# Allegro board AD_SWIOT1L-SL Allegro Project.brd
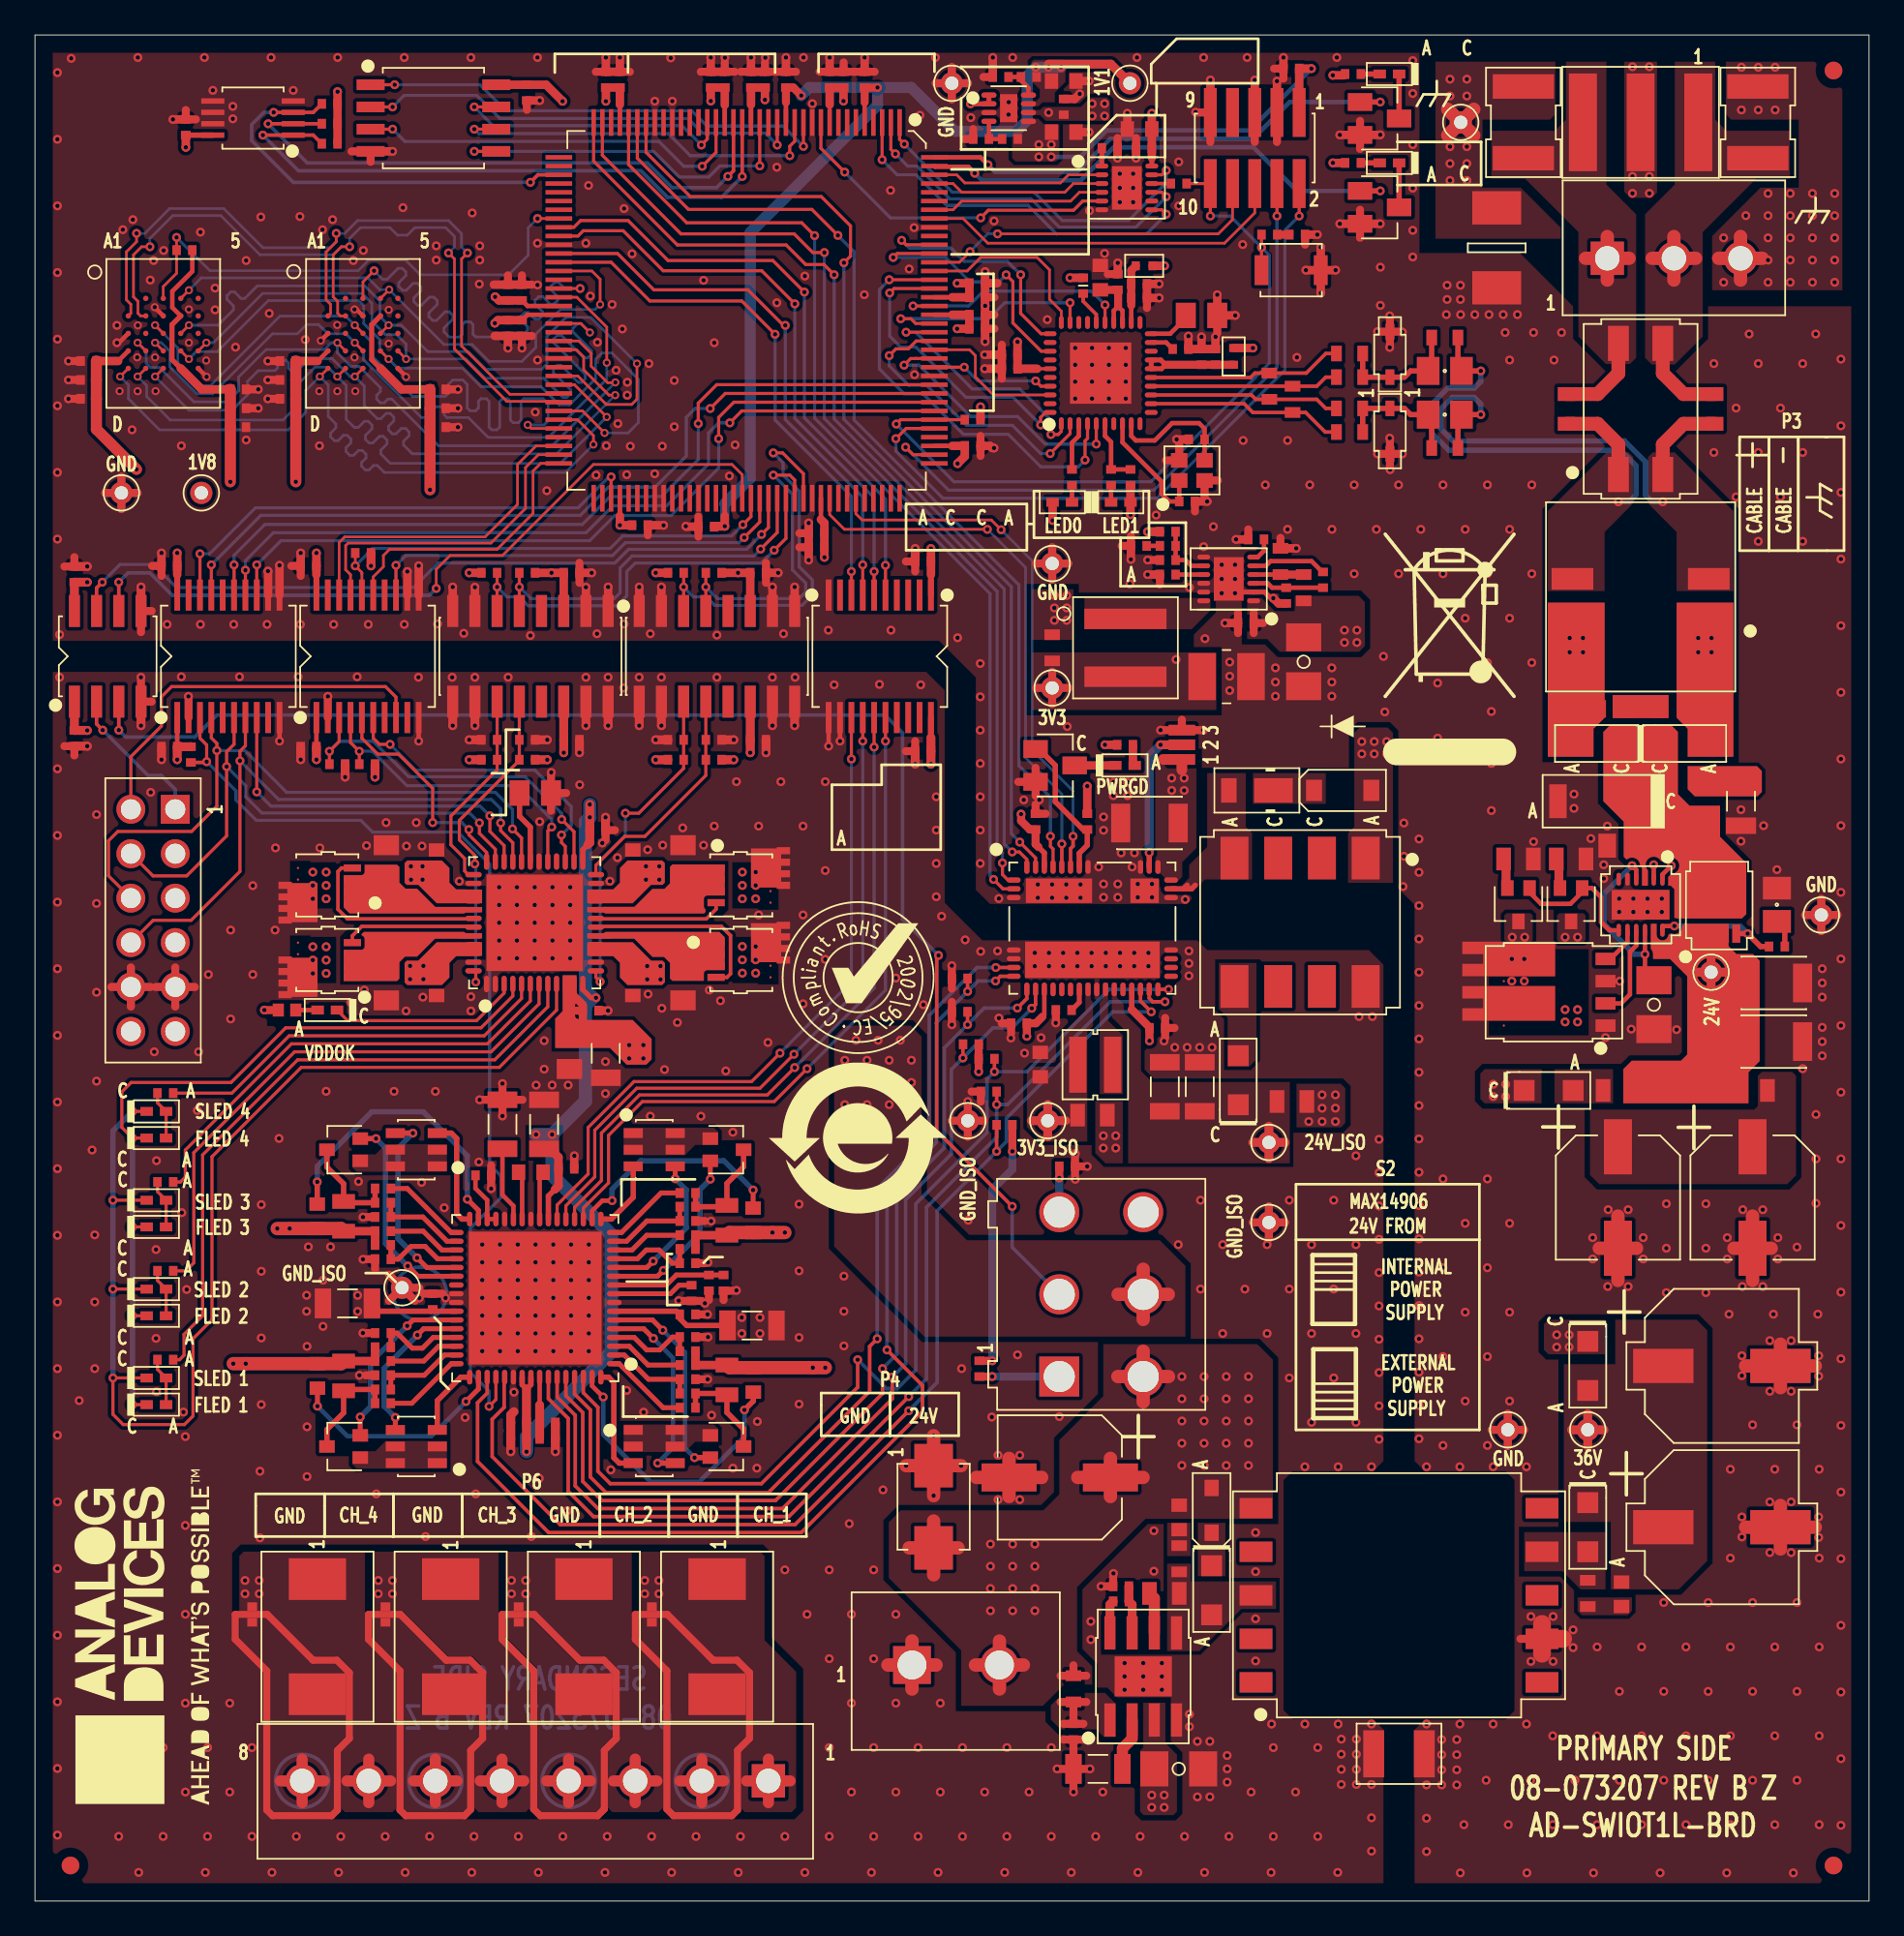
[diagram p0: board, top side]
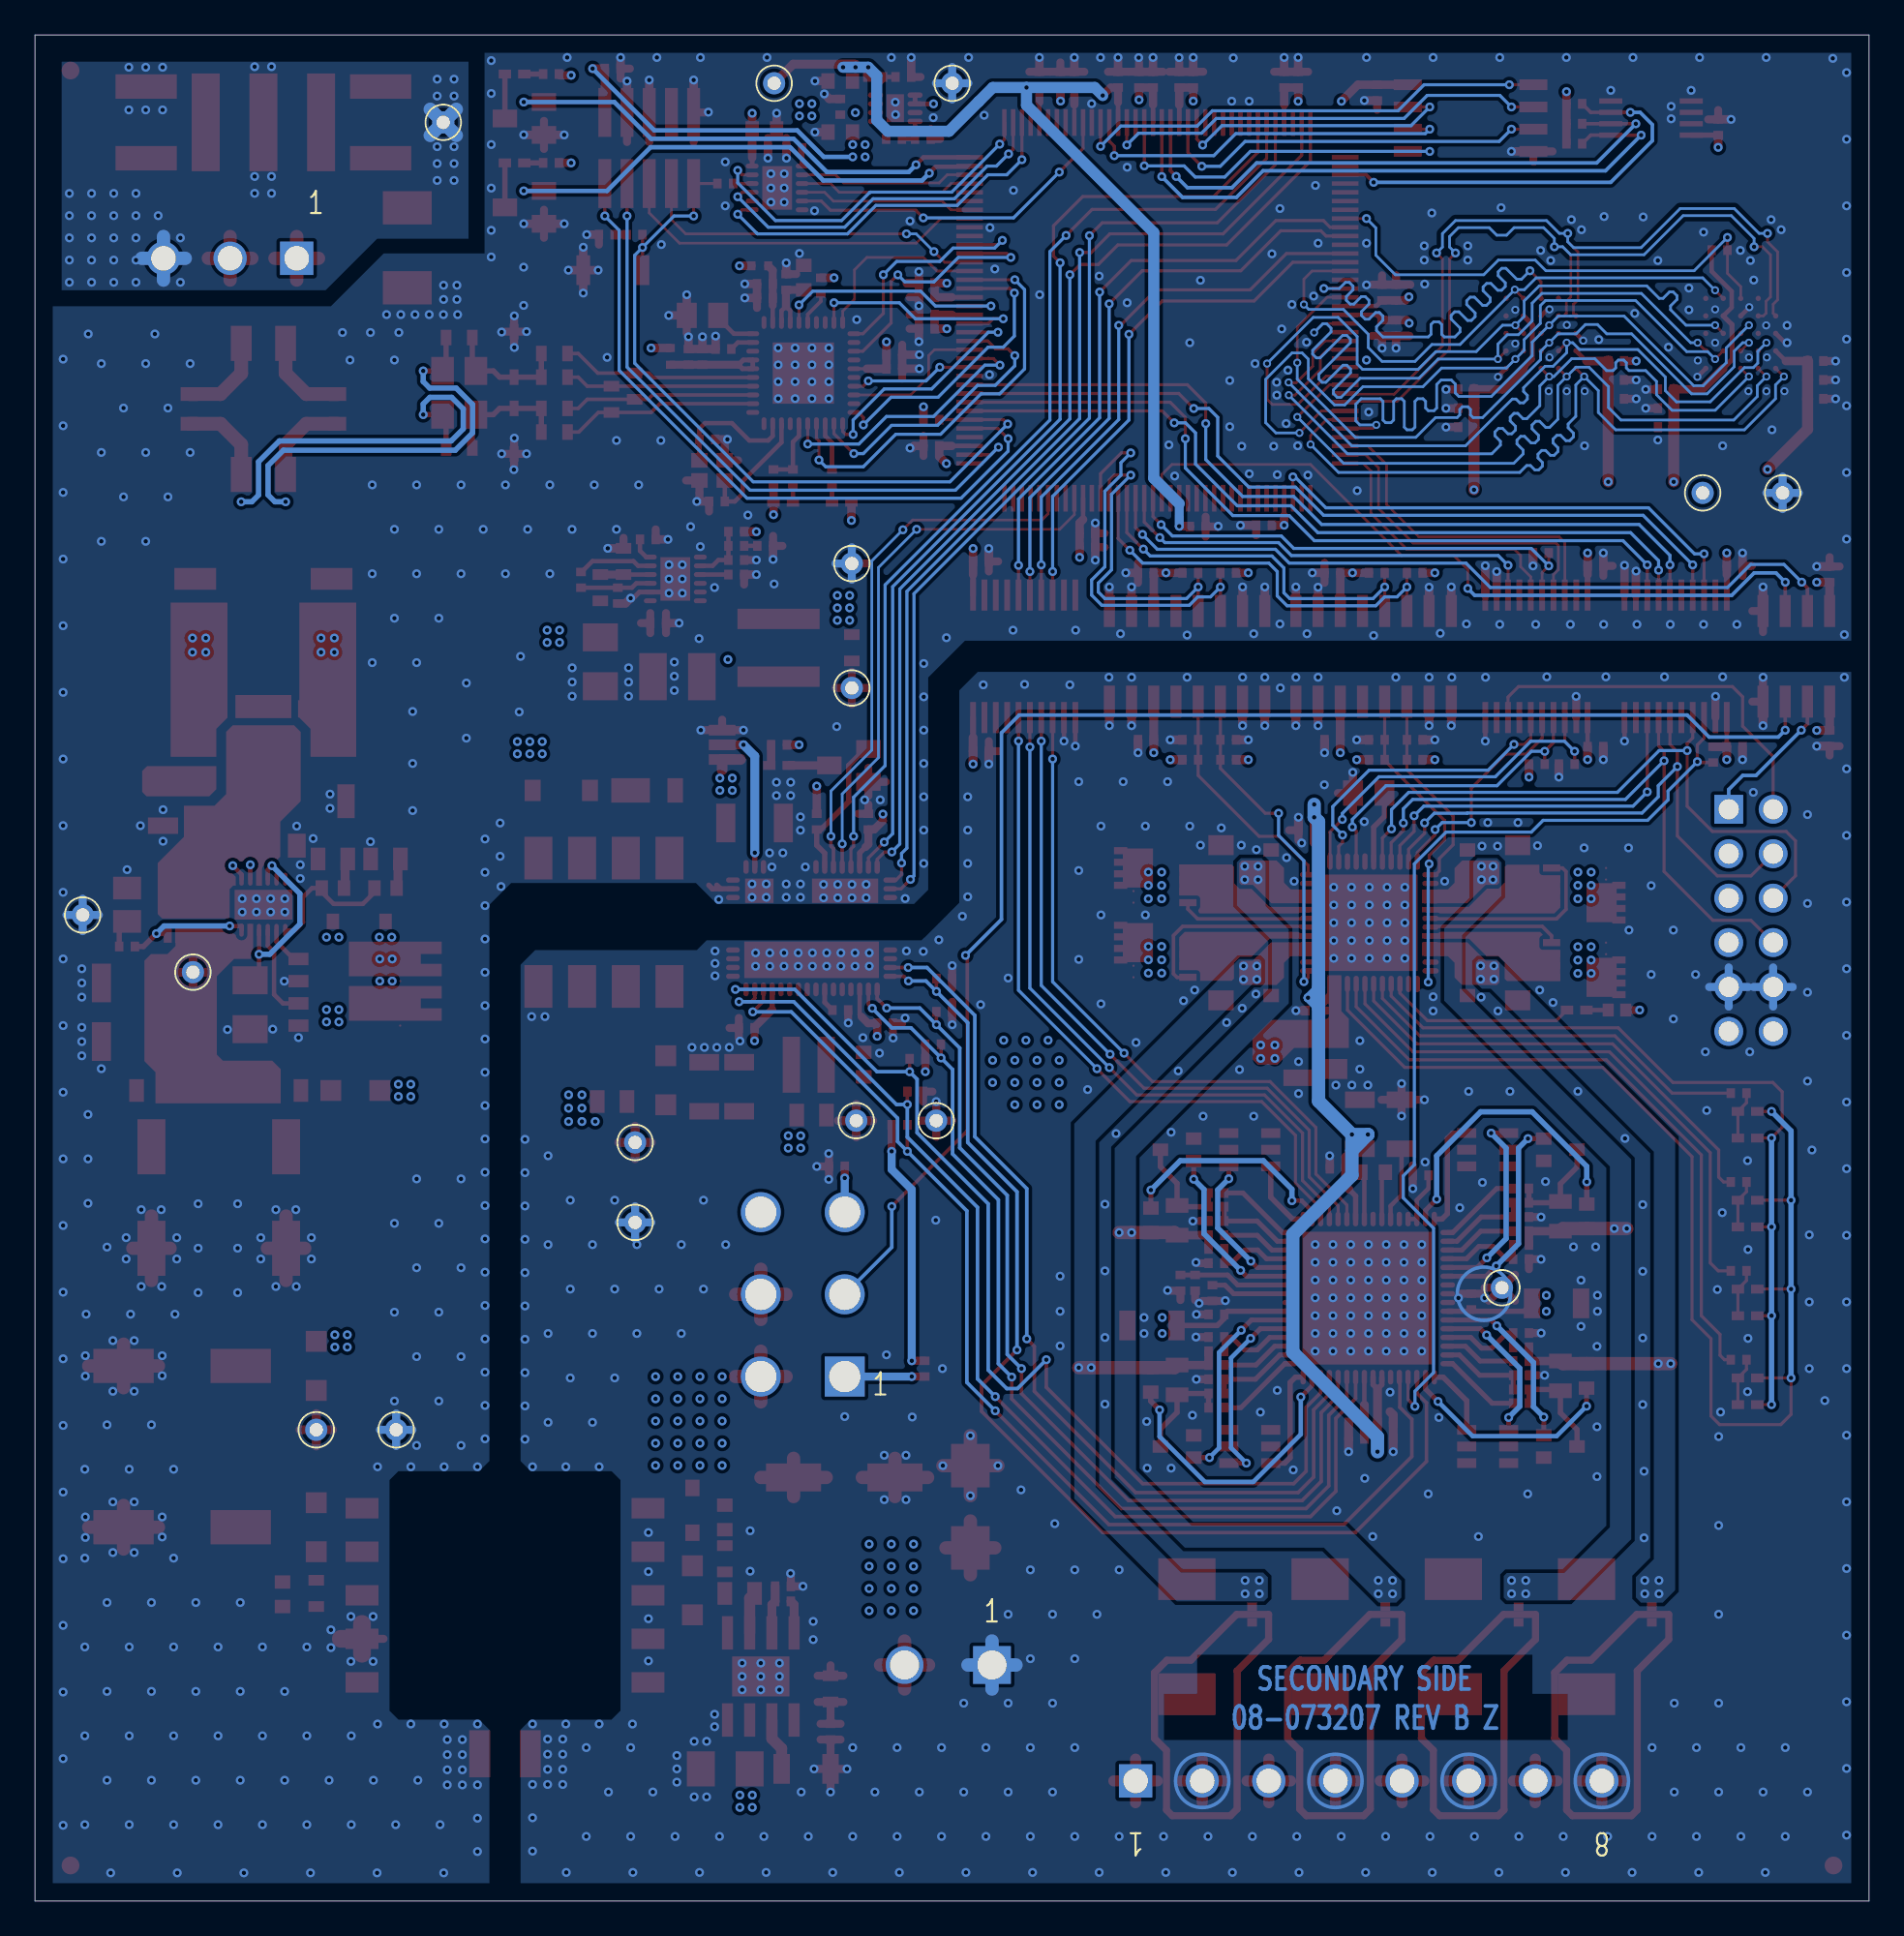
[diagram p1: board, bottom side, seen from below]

Outline 104.9 x 106.68 mm; copper layers: TOP, L2_PWR, L3_GND, BOTTOM. Coordinates in mm from the lower left corner of the outline.
Outline path: 0,106.68 0,0 104.9,0 104.9,106.68 0,106.68

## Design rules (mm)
constraint set DEFAULT: min track width 0.152
net group CLK_CS_MG: nets HYP_CLK HYP_CS0N
net group RESET_CS_MG: nets HYP_CS1N HYP_RESET

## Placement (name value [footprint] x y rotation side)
C1  220pF  [C0603]  41.09 29.79 90 top
C2  220pF  [C0603]  16.14 39.14 270 top
C3  220pF  [C0603]  16.16 30.02 90 top
C4  220pF  [C0603]  41.07 38.92 270 top
C5  0.01uF  [C0402]  37.33 32.24 0 top
C6  0.01uF  [C0402]  37.33 29.83 0 top
C7  0.01uF  [C0402]  37.33 36.47 0 top
C8  0.01uF  [C0402]  37.33 38.88 0 top
C9  0.01uF  [C0402]  19.9 36.69 180 top
C10  0.01uF  [C0402]  19.9 39.11 180 top
C11  0.01uF  [C0402]  19.9 32.47 180 top
C12  0.01uF  [C0402]  19.9 30.06 180 top
C13  0.01uF  [C0402]  35.28 16.38 270 top
C14  0.01uF  [C0402]  27.66 16.38 270 top
C15  0.01uF  [C0402]  20.04 16.38 270 top
C16  0.01uF  [C0402]  12.42 16.38 270 top
C17  0.33UF  [C0603]  28.36 41.66 180 top
C18  10uF  [C1206H71]  41.01 32.9 180 top
C19  0.1UF  [C0402]  37.33 33.54 180 top
C20  10uF  [C1206H71]  26.74 44.41 270 top
C21  0.1UF  [C0402]  37.56 34.76 270 top
C22  0.1UF  [C0402]  38.55 35.34 270 top
C23  0.1UF  [C0402]  29.32 27.35 0 top
C24  10uF  [C1206H71]  64.62 46.55 90 top
C25  2.2UF  [C0402H22]  39.39 35.34 90 top
C26  10uF  [C1206H71]  17.87 34.17 0 top
C27  0.1UF  [C0402]  22.75 34.27 270 top
C28  10uF  [C1206H71]  29.12 44.41 270 top
C29  0.1UF  [C0402]  30.39 41.87 180 top
C30  0.1UF  [C0402]  27.66 27.35 0 top
C31  0.1UF  [C0402]  27.66 26.42 0 top
C32  1UF  [C0805H55]  30.56 48.46 90 top
C33  1UF  [C0805H55]  37.07 59.46 90 top
C34  1UF  [C0805H55]  37.07 52.39 270 top
C35  1UF  [C0805H55]  20.1 59.46 90 top
C36  1UF  [C0805H55]  20.1 52.39 270 top
C37  470PF  [C0603]  22.97 52.47 270 top
C38  470PF  [C0603]  22.97 59.39 90 top
C39  470PF  [C0603]  34.2 59.39 90 top
C40  470PF  [C0603]  34.2 52.47 270 top
C41  0.1UF  [C0402]  31.78 50.9 0 top
C42  1UF  [C0805H55]  28.62 63.34 180 top
C43  10uF  [C1206H71]  32.65 48.46 90 top
C44  0.1UF  [C0402]  32.18 61.22 180 top
C45  0.22uF  [C0805H60]  80.64 87.47 0 top
C46  0.22uF  [C0805H60]  80.64 84.98 0 top
C47  4.7uF  [C1210H87]  63.74 61.63 180 top
C48  10uF  [C1206H71]  66.62 46.55 90 top
C49  4.7uF  [C0603]  57.5 47.82 90 top
C50  15pF  [C0402]  65.9 80.01 0 top
C51  15pF  [C0402]  66.45 83.56 180 top
C52  0.1UF  [C0402]  65.52 88.73 0 top
C53  1UF  [C0805H55]  66.72 90.65 0 top
C54  0.01uF  [C0402]  66.72 88.28 270 top
C55  0.01uF  [C0402]  63.15 91.65 180 top
C56  0.1UF  [C0402]  67.52 88.28 90 top
C57  0.1UF  [C0402]  63.15 92.45 0 top
C58  0.68uF  [C0603]  60.93 92.81 90 top
C59  0.01uF  [C0402]  55.75 87.6 180 top
C60  0.1UF  [C0402]  61.93 92.56 270 top
C61  0.1UF  [C0402]  55.75 88.4 0 top
C62  1uF  [C0402]  38.65 104.13 270 top
C63  1uF  [C0402]  32.65 104.13 270 top
C64  1uF  [C0402]  27.05 89.92 90 top
C65  1uF  [C0402]  53.89 89.89 180 top
C66  0.01uF  [C0402]  39.45 104.13 270 top
C67  0.01uF  [C0402]  33.45 104.13 270 top
C68  0.01uF  [C0402]  27.85 89.92 90 top
C69  0.01uF  [C0402]  53.89 90.69 180 top
C70  0.01uF  [C0402]  27.85 91.96 90 top
C71  0.01uF  [C0402]  53.89 91.69 0 top
C72  0.01uF  [C0402]  40.95 104.13 90 top
C73  0.01uF  [C0402]  45.45 104.13 90 top
C74  1uF  [C0402]  53.89 92.49 0 top
C75  1uF  [C0402]  27.05 91.96 90 top
C76  1uF  [C0402]  41.75 104.13 90 top
C77  1uF  [C0402]  46.25 104.13 90 top
C78  1uF  [C0402]  42.95 104.13 90 top
C79  1uF  [C0402]  47.45 104.13 90 top
C80  1uF  [C0402]  38.39 78.57 180 top
C81  1uF  [C0402]  34.6 78.65 0 top
C82  0.01uF  [C0402]  44.7 78.2 180 top
C83  1uF  [C0402]  44.7 77.4 180 top
C84  1uF  [C0402]  14.47 85.88 0 top
C85  0.1UF  [C0402]  14.47 88.04 180 top
C86  0.1UF  [C0402]  14.47 86.96 180 top
C87  1uF  [C0402]  23.05 84.26 0 top
C88  0.1UF  [C0402]  23.05 85.34 180 top
C89  0.1UF  [C0402]  23.05 86.42 180 top
C90  1uF  [C0402]  3.06 85.88 0 top
C91  0.1UF  [C0402]  3.06 88.04 180 top
C92  0.1UF  [C0402]  3.06 86.96 180 top
C93  1uF  [C0402]  11.62 84.26 0 top
C94  0.1UF  [C0402]  11.62 86.42 180 top
C95  0.1UF  [C0402]  11.62 85.34 180 top
C96  0.1UF  [C0402]  28.13 103.39 270 top
C97  0.1UF  [C0402]  8.63 101.41 90 top
C98  4.7uF  [C0603]  63.18 101.3 0 top
C99  0.1UF  [C0402]  63.43 100.22 180 top
C100  1uF  [C0402]  61.47 100.22 0 top
C101  0.1UF  [C0402]  71.86 104.76 180 top
C102  0.1UF  [C0402]  7.69 76.33 180 top
C103  0.1UF  [C0402]  15.65 76.33 180 top
C104  0.1UF  [C0402]  7.69 65.99 0 top
C105  0.1UF  [C0402]  15.65 65.99 0 top
C106  0.1UF  [C0402]  25.64 41.49 180 top
C107  0.1UF  [C0402]  50.8 76.58 180 top
C108  0.1UF  [C0402]  41.36 75.93 180 top
C109  0.1UF  [C0402]  30.69 75.93 180 top
C110  0.1UF  [C0402]  41.36 66.39 180 top
C111  0.1UF  [C0402]  30.69 66.39 180 top
C112  0.1UF  [C0402]  50.8 65.73 0 top
C113  100pF  [C1812H71]  98.54 101.69 90 top
C114  0.047UF  [C0603#2]  90.19 68.16 180 top
C115  22UF  [CPLSMSQ260H240_A]  98.24 40.22 270 top
C116  10uF  [C1206H71]  65.42 7.55 0 top
C117  150NF  [C1206H71]  97.58 62.87 270 top
C118  0.047uF  [C0805]  90.73 60.33 180 top
C119  0.022UF  [C0805H60]  99.63 56.96 270 top
C120  4.7uF  [C1210H87]  99.46 49.13 0 top
C121  0.1UF  [C0402]  57.23 61.71 270 top
C122  4.7uF  [C1210H87]  99.46 52.49 0 top
C123  1uF  [C0402]  58.84 102.57 90 top
C124  4.7uF  [C0603]  58.84 101.13 0 top
C125  4.7uF  [C0603]  58.84 104.05 0 top
C126  6800pF  [C0402]  63.13 77.47 180 top
C127  0.1UF  [C0402]  64.79 75.83 180 top
C128  0.1UF  [C0402]  64.19 49.91 180 top
C129  0.1UF  [C0402]  56.28 50.18 0 top
C130  2.2UF  [C0402H22]  29.32 26.42 180 top
C131  1uF  [C0402]  71.57 74.63 90 top
C132  47uF  [C1210-2]  68.16 70 0 top
C133  22UF  [CPLSMSQ260H240_A]  90.54 40.22 270 top
C134  33UF  [CPLSMSQ327H276]  96.48 30.59 0 top
C135  2.2uF  [C1206H71]  92.6 51.24 270 top
C136  4.7NF  [C1210H67]  78.02 8.42 0 top
C137  1uF  [C1206]  60.8 7.55 180 top
C138  2.2uF  [C1206H71]  72.57 70.85 270 top
C139  0.1UF  [C0402]  69.26 73.06 180 top
C140  33UF  [CPLSMSQ327H276]  96.48 21.37 0 top
C141  220pF  [C0603]  65.45 21.93 270 top
C142  1uF  [C0402]  53.63 83.19 0 top
C143  100pF  [C1812H71]  85.13 101.69 90 top
C144  22UF  [CPLSMSQ260H240_A]  58.61 24.22 180 top
C145  220pF  [C0603]  90.74 17.54 90 top
C146  0.1UF  [C0402]  2.25 75.85 90 top
C147  0.1UF  [C0402]  2.25 66.47 90 top
C180  0.1UF  [C0402]  70.6 95.27 180 top
CR1  SBAV99WT1G  [SOT323]  39.58 25.98 270 top
CR2  SBAV99WT1G  [SOT323]  39.58 42.95 270 top
CR3  SBAV99WT1G  [SOT323]  17.65 42.95 90 top
CR4  SBAV99WT1G  [SOT323]  17.65 25.98 90 top
D1  SMCJ40CA-TR  [DO214AB_A]  39.02 15.11 270 top
D2  SMCJ40CA-TR  [DO214AB_A]  31.4 15.11 270 top
D3  SMCJ40CA-TR  [DO214AB_A]  23.78 15.11 270 top
D4  SMCJ40CA-TR  [DO214AB_A]  16.16 15.11 270 top
D5  SP4020-01FTG  [SOD323_B]  77.5 88.42 90 top
D6  2038-80-SM-RPLF  [D2038]  91.84 101.69 0 top
D7  PMEG10020AELRX  [SOD123F]  89.32 66.18 180 top
D8  PMEG10020AELRX  [SOD123F]  94.35 66.18 0 top
D9  PTVS58VP1UTP  [SOD128]  89.32 62.87 180 top
D10  US1DWF-7  [SOD123F]  68.82 46.92 90 top
D11  MMSZ5265BT1G  [SOD123-2]  74.8 63.49 0 top
D12  DFLS1200Q-7  [POWERDI123]  69.89 63.49 180 top
D13  BZX384-B51  [SOD323-2]  67.3 22.34 90 top
D14  PMEG10020AELRX  [SOD123F]  67.3 17.76 270 top
D15  PMEG10020AELRX  [SOD123F]  86.58 46.34 0 top
D16  PMEG10020AELRX  [SOD123F]  88.81 21.37 270 top
D17  SMBJ36CA  [DO214AA-5]  51.4 22.54 270 top
D18  PMEG10020AELRX  [SOD123F]  88.81 30.59 270 top
D19  SP4020-01FTG  [SOD323_B]  77.5 84.03 270 top
DS1  APHHS1005CGCK  [LED0402_A]  6.94 45.14 0 top
DS2  APHHS1005LSECK/J3-PF  [LED0402H24]  6.94 43.62 0 top
DS3  APHHS1005CGCK  [LED0402_A]  6.94 40.06 0 top
DS4  APHHS1005LSECK/J3-PF  [LED0402H24]  6.94 38.54 0 top
DS5  APHHS1005CGCK  [LED0402_A]  6.94 34.98 0 top
DS6  APHHS1005LSECK/J3-PF  [LED0402H24]  6.94 33.46 0 top
DS7  APHHS1005CGCK  [LED0402_A]  6.94 29.9 0 top
DS8  APHHS1005LSECK/J3-PF  [LED0402H24]  6.94 28.38 0 top
DS9  APHHS1005CGCK  [LED0402_A]  16.72 50.94 180 top
DS10  APHHS1005CGCK  [LED0402_A]  58.76 79.97 180 top
DS11  APHHS1005LSYCK/J3-PF  [LED0402H24]  62.11 79.97 0 top
DS12  APHHS1005CGCK  [LED0402_A]  62.35 64.92 0 top
DS17  APHHS1005CGCK  [LED0402_A]  77.47 104.45 180 top
DS18  APHHS1005CGCK  [LED0402_A]  77.47 99.37 180 top
E1  100OHM AT 100MEGHZ  [L0402-3]  68.56 88.31 270 top
E2  100OHM AT 100MEGHZ  [L0402-3]  63.44 93.48 180 top
JP1  3PIN_SOLDER_JUMPER  [JPRSLD03]  65.6 66.1 90 top
L1  470UH  [LSML236W362H209]  91.84 85.3 0 top
L2  68UH  [LSMSQ406H197]  91.84 74.56 180 top
L3  100UH  [LSMSQ118H47]  60.65 47.81 180 top
L4  22uH  [LSML208W216H201]  62.37 71.65 270 top
NOREF  -  []  104.9 0 90 top
NOREF#2  -  []  104.9 106.68 180 top
NOREF#3  -  []  52.45 53.34 0 top
NOREF#4  -  []  47.08 52.79 0 top
NOREF#5  -  []  52.31 134.86 0 top
NOREF#6  -  []  -222.25 -146.05 0 top
NOREF#7  -  []  273.7 54.64 0 top
NOREF#8  -  []  51.73 4.15 270 top
NOREF#9  -  []  6.14 15.11 90 top
NOREF#10  -  []  90.19 81.82 0 top
NOREF#11  -  []  15.28 6.87 0 top
NOREF#12  -  []  94.84 88.08 0 top
NOREF#13  -  []  0 0 0 top
NOREF#14  -  []  177.18 229.35 0 top
NOREF#15  -  []  15.28 6.87 0 top
NOREF#16  -  []  0 0 0 top
NOREF#17  -  [unnamed#2]  2.03 2.03 0 top
NOREF#18  -  []  0 106.68 0 top
NOREF#19  -  []  47.06 43.62 0 top
NOREF#20  -  []  0 106.68 270 top
NOREF#21  -  []  104.9 0 90 top
NOREF#22  -  []  104.9 0 0 top
NOREF#23  -  []  544.69 8.64 0 top
NOREF#24  -  []  265.92 42.9 0 top
NOREF#25  -  []  0 0 0 top
NOREF#26  -  []  -222.25 -146.05 0 top
NOREF#27  -  []  -66.41 -190.24 0 top
NOREF#28  -  []  0 106.68 0 top
NOREF#29  -  [unnamed#2]  102.87 2.03 0 top
NOREF#30  -  []  131.44 363.86 0 top
NOREF#31  -  [unnamed#2]  102.87 104.65 0 top
P1  FTSH-105-01-L-DV-K  [CNHDR2X5H245]  69.77 100.22 180 top
P2  SSW-106-01-T-D  [CNRCPT2X6H335LD35]  8.02 62.41 270 top
P3  TBP02R2-381-03BE  [CNCUITBP02R2-381-03]  89.93 93.91 0 top
P4  TBP04R2-500-02BE  [CNCUITBP04R2-500-02]  50.16 13.49 0 top
P6  TBP02R2-381-08BE  [CNCUITBP02R2-381-08]  41.95 6.87 180 top
Q1  ZXMP6A17E6TA  [SOT26-2]  35.42 25.98 270 top
Q2  ZXMP6A17E6TA  [SOT26-2]  35.42 42.95 270 top
Q3  ZXMP6A17E6TA  [SOT26-2]  21.81 42.95 90 top
Q4  ZXMP6A17E6TA  [SOT26-2]  21.81 25.98 90 top
Q5  SI7309DN-T1-GE3  [POWERPAK1212-8_SP]  40.39 58.07 270 top
Q6  SI7309DN-T1-GE3  [POWERPAK1212-8_SP]  40.39 53.8 270 top
Q7  SI7309DN-T1-GE3  [POWERPAK1212-8_SP]  16.72 58.07 90 top
Q8  SI7309DN-T1-GE3  [POWERPAK1212-8_SP]  16.72 53.8 90 top
Q9  PSMN075-100MSEX  [SOT1210]  96.33 56.96 0 top
Q10  BSS123WQ-7-F  [SOT323]  87.86 56.96 180 top
Q11  BSS123WQ-7-F  [SOT323]  84.85 56.96 180 top
Q12  BUK9K29-100E,115  [SOT1205]  86.55 51.95 90 top
Q13  BSS138TA  [SOT23]  58.35 64.92 270 top
Q20  BSS138TA  [SOT23]  76.91 101.91 270 top
Q21  BSS138TA  [SOT23]  76.91 96.83 270 top
R1  2K  [R0402]  37.33 30.64 0 top
R2  2K  [R0402]  37.33 28.2 0 top
R3  2K  [R0402]  37.33 38.07 0 top
R4  2K  [R0402]  37.33 40.48 0 top
R5  2K  [R0402]  19.9 38.29 180 top
R6  2K  [R0402]  19.9 40.73 180 top
R7  2K  [R0402]  19.9 30.87 180 top
R8  2K  [R0402]  19.9 28.46 180 top
R9  10K  [R0402]  37.33 31.43 0 top
R10  10K  [R0402]  37.33 29.02 0 top
R11  10K  [R0402]  37.33 37.28 0 top
R12  10K  [R0402]  37.33 39.69 0 top
R13  10K  [R0402]  19.9 37.51 180 top
R14  10K  [R0402]  19.9 39.92 180 top
R15  10K  [R0402]  19.9 31.66 180 top
R16  10K  [R0402]  19.9 29.24 180 top
R17  100  [R0805]  39.58 29.79 270 top
R18  100  [R0805]  39.58 38.92 90 top
R19  100  [R0805]  17.65 39.14 90 top
R20  100  [R0805]  17.65 30.02 270 top
R21  10K  [R0603]  70.6 86.6 90 top
R22  49.9  [R0603]  75.19 88.47 0 top
R23  4.99K  [R0603]  75.19 85.33 0 top
R24  49.9  [R0603]  75.19 83.98 0 top
R25  4.99K  [R0603]  75.19 87.12 0 top
R26  10K  [R0603]  71.93 85.85 270 top
R27  0  [R0805]  71.89 45.71 180 top
R28  100K  [R0402]  59.4 9.68 270 top
R29  1MEG  [R0603]  59.4 12.13 90 top
R30  5.6K  [R0402]  7.46 46.19 0 top
R31  5.6K  [R0402]  7.46 41.11 0 top
R32  5.6K  [R0402]  7.46 36.03 0 top
R33  5.6K  [R0402]  7.46 30.95 0 top
R34  24.9K  [R0402]  14.42 50.94 0 top
R35  1.5K  [R0402]  59.95 92.35 90 top
R36  4.7MEG  [R2010]  83.61 94.51 270 top
R37  10K  [R0402]  18.77 77.07 0 top
R38  3.3  [R0805]  87.86 59.57 0 top
R39  100  [R0603]  93.61 68.16 180 top
R40  10K  [R0402]  99.63 54.57 180 top
R41  3.3  [R0805]  84.85 59.57 0 top
R42  40.2  [R0805]  95.67 62.87 90 top
R43  28K  [R0402]  56.84 104.28 180 top
R44  23.2K  [R0402]  55.23 104.28 180 top
R45  115K  [R0402]  55.77 100.73 180 top
R46  44.2K  [R0402]  54.11 100.73 180 top
R47  10K  [R0402]  59.04 42 0 top
R48  0  [R0805]  60.48 44.93 180 top
R49  430K  [R0603]  72.57 75.08 90 top
R50  10K  [R0402]  36.65 66.39 180 top
R51  10K  [R0402]  25.98 66.39 180 top
R52  10K  [R0402]  38.82 66.39 0 top
R53  10K  [R0402]  28.15 66.39 0 top
R54  10K  [R0402]  62.12 17.99 180 top
R55  360K  [R0805]  64.6 17.59 0 top
R56  100K  [R0402]  58.84 50.94 180 top
R57  100K  [R0402]  60.19 61.71 270 top
R58  10K  [R0402]  54.02 30.43 90 top
R59  137K  [R0603]  71.24 76.58 90 top
R60  57.6K  [R0402]  64.79 78.28 0 top
R61  18.2K  [R0402]  64.79 76.66 180 top
R62  105K  [R0402]  69.85 77.84 0 top
R63  15.4K  [R0402]  64.79 77.47 180 top
R64  10K  [R0402]  73.67 75.53 90 top
R65  0  [R0603]  58.18 71.65 90 top
R66  3.3  [R0805]  98.24 46.34 0 top
R67  100K  [R0402]  62.12 17.13 180 top
R68  100  [R0603]  65.45 19.57 270 top
R69  10K  [R0402]  19 64.99 180 top
R70  10K  [R0402]  17.29 64.99 0 top
R71  1MEG  [R0603]  80.64 83.07 0 top
R72  1MEG  [R0603]  80.64 89.38 0 top
R73  10K  [R0603]  87.59 85.3 270 top
R74  10K  [R0603]  96.08 85.3 270 top
R75  100K  [R0402]  54.43 48.15 0 top
R76  100K  [R0402]  52.89 50.84 180 top
R77  100K  [R0402]  53.53 48.98 180 top
R78  100K  [R0402]  54.55 46.27 180 top
R79  100K  [R0402]  55.45 44.37 180 top
R80  100K  [R0402]  52.89 52.74 180 top
R81  1K  [R0402]  62.35 66.1 0 top
R82  10K  [R0402]  8.55 94.38 180 top
R83  100  [R0603]  88.81 17.59 270 top
R84  10K  [R0402]  8.92 65.54 270 top
R94  10K  [R0402]  16.86 102.75 180 top
R95  10K  [R0402]  16.86 101.61 180 top
R96  10K  [R0402]  16.86 100.47 180 top
R102  4.7K  [R0402]  59.31 81.39 90 top
R104  10K  [R0402]  62.66 81.39 90 top
R105  4.7K  [R0402]  61.55 81.39 90 top
R106  0  [R0402]  65.42 98.19 0 top
R116  1K  [R0402]  75.39 104.45 0 top
R117  1K  [R0402]  75.39 99.37 0 top
R123  0  [R0805]  90.54 46.34 180 top
R125  10K  [R0402]  53.63 84.69 180 top
R126  10  [R0402]  72.2 95.27 0 top
R127  10K  [R0402]  38.82 75.93 180 top
R128  10K  [R0402]  28.15 75.93 180 top
R129  10K  [R0402]  36.65 75.93 0 top
R130  10K  [R0402]  25.98 75.93 0 top
R132  10K  [R0402]  36.65 65.25 0 top
R133  10K  [R0402]  25.98 65.25 0 top
R134  10K  [R0402]  38.82 65.25 180 top
R135  10K  [R0402]  28.15 65.25 180 top
S1  B3U-1000P  [SWSML118W98H69]  71.85 93.24 0 top
S2  MS22BNW03  [SWTHL449W500H561]  58.59 29.98 0 top
T1  ZA9644-AED  [TSML430W364H394]  72.36 55.95 180 top
T2  750315836  [TSMSQ530H505]  78.02 17.48 90 top
TP1  TESTPAD  [TPC50D30]  21 35.06 0 top
TP2  TESTPAD  [TPC50D30]  81.55 101.69 0 top
TP3  TESTPAD  [TPC50D30]  95.87 53.1 0 top
TP4  TESTPAD  [TPC50D30]  102.17 56.37 0 top
TP5  TESTPAD  [TPC50D30]  88.81 26.94 0 top
TP6  TESTPAD  [TPC50D30]  84.24 26.94 0 top
TP7  TESTPAD  [TPC50D30]  70.58 43.37 0 top
TP8  TESTPAD  [TPC50D30]  70.58 38.79 0 top
TP9  TESTPAD  [TPC50D30]  57.93 44.61 0 top
TP10  TESTPAD  [TPC50D30]  53.36 44.61 0 top
TP11  TESTPAD  [TPC50D30]  58.18 69.35 0 top
TP12  TESTPAD  [TPC50D30]  58.18 76.46 0 top
TP13  TESTPAD  [TPC50D30]  9.51 80.5 0 top
TP14  TESTPAD  [TPC50D30]  4.94 80.5 0 top
TP15  TESTPAD  [TPC50D30]  62.63 103.92 0 top
TP16  TESTPAD  [TPC50D30]  52.44 103.92 0 top
U1  MAX32650GCE+  [QFP144-4]  40.7 90.94 180 top
U2  AD74413RBCPZ  [QFN64_9X9_PAD7_6X7_6]  28.62 34.47 90 top
U3  MAX14906ATM+  [QFN48_7X7_PAD5_5X5_5]  28.58 55.93 0 top
U4  ADT75BRMZ  [MSOP8]  12.47 101.93 90 top
U5  MAXQ1065GTC+  [DFN12_3X3_PAD2_5X1_7]  62.45 97.94 270 top
U6  MAX14483AAP+  [SSOP20-6]  11.06 71.16 0 top
U7  MAX14483AAP+  [SSOP20-6]  19.02 71.16 0 top
U8  ADIN1110CCPZ  [QFN40_6X6_PAD3_5X3_5]  60.95 87.35 0 top
U9  S80KS5122GABHM020  [BGA24_8X6]  7.34 89.62 270 top
U10  S80KS5122GABHM020  [BGA24_8X6]  18.76 89.62 270 top
U11  MX25U6432FM2I02  [SOP8_A]  22.79 101.93 270 top
U12  MAX14933ASE+  [SO16NB-2]  39.01 71.16 180 top
U13  MAX14933ASE+  [SO16NB-2]  28.34 71.16 180 top
U14  MAX14483AAP+  [SSOP20-6]  48.32 71.16 180 top
U15  LT8304IS8E#PBF  [SO8NB_PAD3_27X2_28-05-08-1857]  63.39 12.84 0 top
U16  MAX17761ATC+  [DFN12_3X3_PAD2_5X1_7]  68.28 75.58 90 top
U17  ADP225ACPZ  [QFN8_2X2_PAD1_6X1]  55.69 102.49 270 top
U18  MAX12930EASA+  [SO8NB-5]  4.16 71.16 0 top
U19  LTC9111RDE#PBF  [DFN12_4X3_PAD3_3X1_7-05-08-1695]  91.84 56.96 180 top
U25  ADP1032ACPZ-5  [QFN41_7X9_3PAD]  60.48 55.62 270 top
Y1  25MEGHZ  [YSML79W63H20]  66.17 81.79 0 top

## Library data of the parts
C1-C4 = CAP: User Part Number: UPN; Tolerance: 5; alternate symbols: (C0603L); part number: CAP_SM-220PF,100V,5,E038248,C0603; tolerance: 5
C5-C16 C54 C55 C59 C66-C73 C82 = CAP: User Part Number: UPN; Tolerance: 10; alternate symbols: (C0402L); part number: CAP_SM-0.01UF,100V,10,E032295,C0402; tolerance: 10
C17 = CAP: User Part Number: UPN; Tolerance: 10; alternate symbols: (C0603L); part number: CAP_SM-0.33UF,10V,10,E060591,C0603; tolerance: 10
C18 C20 C24 C26 C28 C43 C48 = CAP: User Part Number: UPN; Tolerance: 10; alternate symbols: (C1206L); part number: CAP_SM-10UF,50V,10,E026881,C1206H71; tolerance: 10
C19 C21-C23 C27 C29-C31 C41 C44 C52 C56 C57 C60 C61 C85 C86 C88 C89 C91 C92 C94-C97 C99 C101-C112 C121 C127-C129 C139 C146 C147 C180 = CAP: User Part Number: UPN; Tolerance: 10; alternate symbols: (C0402L); part number: CAP_SM-0.1UF,50V,10,E048331,C0402; tolerance: 10
C25 C130 = CAP: User Part Number: UPN; Tolerance: 10; alternate symbols: (C0402L); part number: CAP_SM-2.2UF,10V,10,E060492,C0402H22; tolerance: 10
C32-C36 C42 C53 = CAP: User Part Number: UPN; Tolerance: 10; alternate symbols: (C0805H55); part number: CAP_SM-1UF,100V,10,E048499,C0805H55; tolerance: 10
C37-C40 = CAP: User Part Number: UPN; Tolerance: 10; alternate symbols: (C0603L); part number: CAP_SM-470PF,100V,10,E049432,C0603; tolerance: 10
C45 C46 = CAP: Tolerance: 5; User Part Number: UPN; alternate symbols: (C0805H60); part number: CAP_SM-0.22UF,100V,5,E018909,C0805H60; tolerance: 5
C47 C120 C122 = CAP: Tolerance: 10; User Part Number: UPN; alternate symbols: (C1210H87); part number: CAP_SM-4.7UF,100V,10,E033812,C1210H87; tolerance: 10
C49 C98 C124 C125 = CAP: User Part Number: UPN; Tolerance: 10; alternate symbols: (C0603L); part number: CAP_SM-4.7UF,10V,10,E030749,C0603; tolerance: 10
C50 C51 = CAP: User Part Number: UPN; Tolerance: 1; alternate symbols: (C0402L); part number: CAP_SM-15PF,50V,1,E020722,C0402; tolerance: 1
C58 = CAP: User Part Number: UPN; Tolerance: 10; alternate symbols: (C0603L); part number: CAP_SM-0.68UF,10V,10,E035107,C0603; tolerance: 10
C62-C65 C74-C81 C83 C84 C87 C90 C93 C100 C123 C131 C142 = CAP: User Part Number: UPN; Tolerance: 10; alternate symbols: (C0402L); part number: CAP_SM-1UF,16V,10,E019219,C0402; tolerance: 10
C113 C143 = CAP: Tolerance: 5; User Part Number: UPN; alternate symbols: (C1812H71); part number: CAP_SM-100PF,3000V,5,E023439,C1812H71; tolerance: 5
C114 = CAP: User Part Number: UPN; Tolerance: 10; alternate symbols: (C0603); part number: CAP_SM-0.047UF,100V,10,E045169,C0603; tolerance: 10
C115 C133 C144 = CAPP: Tolerance: 20; User Part Number: UPN; alternate symbols: (CPLSMSQ260H240_A); part number: CAPP_SM-22UF,50V,20,E061438,CPLSMSQ260H240_A; tolerance: 20
C116 = CAP: Tolerance: 10; User Part Number: UPN; alternate symbols: (C1206L); part number: CAP_SM-10UF,50V,10,E026881,C1206H71; tolerance: 10
C117 = CAP: Tolerance: 10; User Part Number: UPN; alternate symbols: (C1206H71L); part number: CAP_SM-150NF,100V,10,E057967,C1206H71; tolerance: 10
C118 = CAP: User Part Number: UPN; Tolerance: 10; alternate symbols: (C0805L); part number: CAP_SM-0.047UF,100V,10,E025410,C0805; tolerance: 10
C119 = CAP: Tolerance: 5; User Part Number: UPN; alternate symbols: (C0805H60); part number: CAP_SM-0.022UF,100V,5,E049287,C0805H60; tolerance: 5
C126 = CAP: User Part Number: UPN; Tolerance: 10; alternate symbols: (C0402L); part number: CAP_SM-6800PF,50V,10,E034944,C0402; tolerance: 10
C132 = CAP: Tolerance: 10; User Part Number: UPN; alternate symbols: (C1210-2); part number: CAP_SM-47UF,10V,10,E011546,C1210-2; tolerance: 10
C134 C140 = CAPP: User Part Number: UPN; Tolerance: 20; alternate symbols: (CPLSMSQ327H276); part number: CAPP_SM-33UF,50V,20,E061439,CPLSMSQ327H276; tolerance: 20
C135 C138 = CAP: Tolerance: 10; User Part Number: UPN; alternate symbols: (C1206H71); part number: CAP_SM-2.2UF,50V,10,E026115,C1206H71; tolerance: 10
C136 = CAP: Tolerance: 10; User Part Number: UPN; alternate symbols: (C1210H67); part number: CAP_SM-4.7NF,1500V,10,E060908,C1210H67; tolerance: 10
C137 = CAP: User Part Number: UPN; Tolerance: 10; alternate symbols: (C1206L); part number: CAP_SM-1UF,25V,10,E029793,C1206; tolerance: 10
C141 C145 = CAP: User Part Number: UPN; Tolerance: 5; alternate symbols: (C0603L); part number: CAP_SM-220PF,50V,5,E000417,C0603; tolerance: 5
CR1-CR4 = DIOBAV99LT1: User Part Number: UPN; Tolerance: N/A; alternate symbols: (SOT323); part number: DIOBAV99LT1_SM-SBAV99WT1G,100V,N/A,E052099,SOT323; tolerance: N/A
D1-D4 = DIOZNR_V2: User Part Number: UPN; Tolerance: N/A; alternate symbols: (DO214AB_A); part number: DIOZNR_V2_SM-SMCJ40CA-TR,40V,N/A,E029925,DO214AB_A; tolerance: N/A
D5 D19 = DIOZNR_V4: Tolerance: N/A; User Part Number: UPN; alternate symbols: (SOD323_B); part number: DIOZNR_V4_SM-SP4020-01FTG,3.3V,N/A,E028177,SOD323_B; tolerance: N/A
D6 = DIOGDT3P: User Part Number: UPN; Tolerance: N/A; alternate symbols: (D2038); part number: DIOGDT3P_SM-2038-80-SM-RPLF,800V,N/A,E048971,D2038; tolerance: N/A
D7 D8 D14-D16 D18 = DIOSCHOTTKY: Tolerance: N/A; User Part Number: UPN; alternate symbols: (SOD123F); part number: DIOSCHOTTKY_SM-PMEG10020AELRX,100V,N/A,E035075,SOD123F; tolerance: N/A
D9 = DIOZNR: User Part Number: UPN; Tolerance: N/A; alternate symbols: (SOD128); part number: DIOZNR_SM-PTVS58VP1UTP,93.6V,N/A,E049291,SOD128; tolerance: N/A
D10 = DIO: Tolerance: N/A; User Part Number: UPN; alternate symbols: (SOD123F); part number: DIO_SM-US1DWF-7,200V,N/A,E034779,SOD123F; tolerance: N/A
D11 = DIOZNR: User Part Number: UPN; Tolerance: N/A; alternate symbols: (SOD123-2); part number: DIOZNR_SM-MMSZ5265BT1G,62V,N/A,E034839,SOD123-2; tolerance: N/A
D12 = DIOSCHOTTKY: User Part Number: UPN; Tolerance: N/A; alternate symbols: (POWERDI123); part number: DIOSCHOTTKY_SM-DFLS1200Q-7,200V,N/A,E034778,POWERDI123; tolerance: N/A
D13 = DIOZNR: Tolerance: 2; User Part Number: UPN; alternate symbols: (SOD323-2); part number: DIOZNR_SM-BZX384-B51,51V,2,E060761,SOD323-2; tolerance: 2
D17 = DIO_V3: Tolerance: N/A; User Part Number: UPN; alternate symbols: (DO214AA-5); part number: DIO_V3_SM-SMBJ36CA,N/A,N/A,E019417,DO214AA-5; tolerance: N/A
DS1 DS3 DS5 DS7 DS9 DS10 DS12 DS17 DS18 = DIOLED: User Part Number: UPN; Tolerance: N/A; alternate symbols: (LED0402_A); part number: DIOLED_SM-APHHS1005CGCK,2.1V,N/A,E029804,LED0402_A; tolerance: N/A
DS2 DS4 DS6 DS8 = DIOLED: User Part Number: UPN; Tolerance: N/A; alternate symbols: (LED0402H24); part number: DIOLED_SM-APHHS1005LSECK/J3-PF,1.8V,N/A,E032957,LED0402H24; tolerance: N/A
DS11 = DIOLED: User Part Number: UPN; Tolerance: N/A; alternate symbols: (LED0402H24); part number: DIOLED_SM-APHHS1005LSYCK/J3-PF,1.85V,N/A,E032958,LED0402H24; tolerance: N/A
E1 E2 = FERRITE: Tolerance: 25; User Part Number: UPN; alternate symbols: (L0402-3); part number: FERRITE_SM-100OHM AT 100MEGHZ,25,E029145,L0402-3; tolerance: 25
JP1 = NC3P_JMPR: Tolerance: N/A; User Part Number: UPN; alternate symbols: (JPRSLD03); part number: NC3P_JMPR_SM-3PIN_SOLDER_JUMPER,E005606,JPRSLD03; tolerance: N/A
L1 = CHOKE4P_V5: User Part Number: UPN; Tolerance: 50; alternate symbols: (LSML236W362H209); part number: CHOKE4P_V5_SM-470UH,50,E032119,LSML236W362H209; tolerance: 50
L2 = IND_4P_V4: User Part Number: UPN; Tolerance: 20; alternate symbols: (LSMSQ406H197); part number: IND_4P_V4_SM-68UH,20,E061378,LSMSQ406H197; tolerance: 20
L3 = IND: Tolerance: 20; User Part Number: UPN; alternate symbols: (LSMSQ118H47); part number: IND_SM-100UH,20,E029287,LSMSQ118H47; tolerance: 20
L4 = IND: Tolerance: 20; User Part Number: UPN; alternate symbols: (LSML208W216H201); part number: IND_SM-22UH,20,E021231,LSML208W216H201; tolerance: 20
P1 = CN10P_ODD_EVEN: Tolerance: N/A; User Part Number: UPN; alternate symbols: (CNHDR2X5H245); part number: CN10P_ODD_EVEN_SM-FTSH-105-01-L-DV-K,E023407,CNHDR2X5H245; tolerance: N/A
P2 = CN12P: Tolerance: N/A; User Part Number: UPN; alternate symbols: (CNRCPT2X6H335LD35); part number: CN12P_TH-SSW-106-01-T-D,E015549,CNRCPT2X6H335LD35; tolerance: N/A
P3 = CN3P: User Part Number: UPN; Tolerance: N/A; alternate symbols: (CNCUITBP02R2-381-03); part number: CN3P_TH-TBP02R2-381-03BE,E061218,CNCUITBP02R2-381-03; tolerance: N/A
P4 = CN2P: User Part Number: UPN; Tolerance: N/A; alternate symbols: (CNCUITBP04R2-500-02); part number: CN2P_TH-TBP04R2-500-02BE,E060556,CNCUITBP04R2-500-02; tolerance: N/A
P6 = CN8P_A: User Part Number: UPN; Tolerance: N/A; alternate symbols: (CNCUITBP02R2-381-08); part number: CN8P_A_TH-TBP02R2-381-08BE,E060555,CNCUITBP02R2-381-08; tolerance: N/A
Q1-Q4 = TRANPMOSFET_V16: User Part Number: UPN; Tolerance: N/A; alternate symbols: (SOT26-2); part number: TRANPMOSFET_V16_SM-ZXMP6A17E6TA,E028509,SOT26-2; tolerance: N/A
Q5-Q8 = TRANPMOSFET_V9: Tolerance: N/A; User Part Number: UPN; alternate symbols: (POWERPAK1212-8_SP); part number: TRANPMOSFET_V9_SM-SI7309DN-T1-GE3,E060489,POWERPAK1212-8_SP; tolerance: N/A
Q9 = TRANNMOSFET_V15: Tolerance: N/A; User Part Number: UPN; alternate symbols: (SOT1210); part number: TRANNMOSFET_V15_SM-PSMN075-100MSEX,E033196,SOT1210; tolerance: N/A
Q10 Q11 = TRANNMOSFET_V8: User Part Number: UPN; Tolerance: N/A; alternate symbols: (SOT323); part number: TRANNMOSFET_V8_SM-BSS123WQ-7-F,E057606,SOT323; tolerance: N/A
Q12 = TRANNMOSFET_DUAL: Tolerance: N/A; User Part Number: UPN; alternate symbols: (SOT1205); part number: TRANNMOSFET_DUAL_SM-BUK9K29-100E,115,E061300,SOT1205; tolerance: N/A
Q13 Q20 Q21 = TRANBSS138: User Part Number: UPN; Tolerance: N/A; alternate symbols: (SOT23); part number: TRANBSS138_SM-BSS138-7-F,E004635,SOT23; tolerance: N/A
R1 R3 R5 R7 = RES: User Part Number: UPN; Tolerance: 1; alternate symbols: (R0402L); part number: RES_SM-2K,E003752,1/10W,1,R0402; tolerance: 1
R2 R4 R6 R8 = RES: User Part Number: UPN; Tolerance: 0.1; alternate symbols: (R0402L); part number: RES_SM-2K,E031286,1/16W,0.1,R0402; tolerance: 0.1
R9-R16 R37 R40 R47 R50-R54 R58 R64 R69 R70 R82 R84 R94-R96 R104 R125 R127-R130 R132-R135 = RES: User Part Number: UPN; Tolerance: 1; alternate symbols: (R0402L); part number: RES_SM-10K,E003751,1/10W,1,R0402; tolerance: 1
R17-R20 = RES: User Part Number: UPN; Tolerance: 0.1; alternate symbols: (R0805L); part number: RES_SM-100,E030091,1/8W,0.1,R0805; tolerance: 0.1
R21 R26 R73 R74 = RES: User Part Number: UPN; Tolerance: 1; alternate symbols: (R0603L); part number: RES_SM-10K,E003671,1/10W,1,R0603; tolerance: 1
R22 R24 = RES: User Part Number: UPN; Tolerance: 1; alternate symbols: (R0603L); part number: RES_SM-49.9,E003673,1/10W,1,R0603; tolerance: 1
R23 R25 = RES: User Part Number: UPN; Tolerance: 1; alternate symbols: (R0603L); part number: RES_SM-4.99K,E003726,1/10W,1,R0603; tolerance: 1
R27 R48 R123 = RES: User Part Number: UPN; Tolerance: JUMPER; alternate symbols: (R0805L); part number: RES_SM-0,E055446,1/2W,JUMPER,R0805; tolerance: JUMPER
R28 R56 R57 R67 R75-R80 = RES: User Part Number: UPN; Tolerance: 5; alternate symbols: (R0402L); part number: RES_SM-100K,E003464,1/10W,5,R0402; tolerance: 5
R29 R71 R72 = RES: User Part Number: UPN; Tolerance: 1; alternate symbols: (R0603L); part number: RES_SM-1MEG,E003682,1/10W,1,R0603; tolerance: 1
R30-R33 = RES: User Part Number: UPN; Tolerance: 5; alternate symbols: (R0402L); part number: RES_SM-5.6K,E015673,1/16W,5,R0402; tolerance: 5
R34 = RES: User Part Number: UPN; Tolerance: 1; alternate symbols: (R0402); part number: RES_SM-24.9K,E007443,1/10W,1,R0402; tolerance: 1
R35 = RES: User Part Number: UPN; Tolerance: 1; alternate symbols: (R0402L); part number: RES_SM-1.5K,E003782,1/10W,1,R0402; tolerance: 1
R36 = RES: Tolerance: 5; User Part Number: UPN; alternate symbols: (R2010); part number: RES_SM-4.7MEG,E031023,1/2W,5,R2010; tolerance: 5
R38 R41 R66 = RES: User Part Number: UPN; Tolerance: 5; alternate symbols: (R0805L); part number: RES_SM-3.3,E054581,1/2W,5,R0805; tolerance: 5
R39 = RES: User Part Number: UPN; Tolerance: 1; alternate symbols: (R0603); part number: RES_SM-100,E003668,1/10W,1,R0603; tolerance: 1
R42 = RES: User Part Number: UPN; Tolerance: 1; alternate symbols: (R0805L); part number: RES_SM-40.2,E003621,1/8W,1,R0805; tolerance: 1
R43 = RES: User Part Number: UPN; Tolerance: 1; alternate symbols: (R0402L); part number: RES_SM-28K,E010020,1/10W,1,R0402; tolerance: 1
R44 = RES: User Part Number: UPN; Tolerance: 1; alternate symbols: (R0402L); part number: RES_SM-23.2K,E036030,1/10W,1,R0402; tolerance: 1
R45 = RES: User Part Number: UPN; Tolerance: 1; alternate symbols: (R0402L); part number: RES_SM-115K,E025179,1/10W,1,R0402; tolerance: 1
R46 = RES: User Part Number: UPN; Tolerance: 1; alternate symbols: (R0402L); part number: RES_SM-44.2K,E023712,1/10W,1,R0402; tolerance: 1
R49 = RES: User Part Number: UPN; Tolerance: 1; alternate symbols: (R0603L); part number: RES_SM-430K,E011184,1/10W,1,R0603; tolerance: 1
R55 = RES: User Part Number: UPN; Tolerance: 1; alternate symbols: (R0805L); part number: RES_SM-360K,E057196,1/8W,1,R0805; tolerance: 1
R59 = RES: User Part Number: UPN; Tolerance: 1; alternate symbols: (R0603L); part number: RES_SM-137K,E044643,1/10W,1,R0603; tolerance: 1
R60 = RES: User Part Number: UPN; Tolerance: 1; alternate symbols: (R0402L); part number: RES_SM-57.6K,E022063,1/16W,1,R0402; tolerance: 1
R61 = RES: User Part Number: UPN; Tolerance: 1; alternate symbols: (R0402L); part number: RES_SM-18.2K,E010424,1/10W,1,R0402; tolerance: 1
R62 = RES: User Part Number: UPN; Tolerance: 1; alternate symbols: (R0402L); part number: RES_SM-105K,E019614,1/16W,1,R0402; tolerance: 1
R63 = RES: User Part Number: UPN; Tolerance: 1; alternate symbols: (R0402L); part number: RES_SM-15.4K,E039024,1/10W,1,R0402; tolerance: 1
R65 = RES: User Part Number: UPN; Tolerance: JUMPER; alternate symbols: (R0603L); part number: RES_SM-0,E006826,1/10W,JUMPER,R0603; tolerance: JUMPER
R68 R83 = RES: User Part Number: UPN; Tolerance: 1; alternate symbols: (R0603L); part number: RES_SM-100,E028138,1/4W,1,R0603; tolerance: 1
R81 R116 R117 = RES: User Part Number: UPN; Tolerance: 1; alternate symbols: (R0402L); part number: RES_SM-1K,E003763,1/10W,1,R0402; tolerance: 1
R102 R105 = RES: User Part Number: UPN; Tolerance: 5; alternate symbols: (R0402L); part number: RES_SM-4.7K,E042730,1/10W,5,R0402; tolerance: 5
R106 = RES: User Part Number: UPN; Tolerance: JUMPER; alternate symbols: (R0402L); part number: RES_SM-0,E003438,1/10W,JUMPER,R0402; tolerance: JUMPER
R126 = RES: User Part Number: UPN; Tolerance: 1; alternate symbols: (R0402L); part number: RES_SM-10,E003768,1/10W,1,R0402; tolerance: 1
S1 = SWSPST2PIN_V2: Tolerance: N/A; User Part Number: UPN; alternate symbols: (SWSML118W98H69); part number: SWSPST2PIN_V2_SM-B3U-1000P,E016303,SWSML118W98H69; tolerance: N/A
S2 = SWDPDT_V5: Tolerance: N/A; alternate symbols: (SWTHL449W500H561); part number: SWDPDT_V5_TH-MS22BNW03,E061775,SWTHL449W500H561; tolerance: N/A
T1 = XFMR8P_V15: User Part Number: UPN; Tolerance: N/A; alternate symbols: (TSML430W364H394); part number: XFMR8P_V15_SM-ZA9644-AED,E039190,TSML430W364H394; tolerance: N/A
T2 = XFMR10P_V22: User Part Number: UPN; Tolerance: N/A; alternate symbols: (TSMSQ530H505); part number: XFMR10P_V22_SM-750315836,E061427,TSMSQ530H505; tolerance: N/A
TP1-TP16 = NCTESTPAD: Tolerance: N/A; User Part Number: UPN; alternate symbols: (TPC50D30); part number: NCTESTPAD_TH-TESTPAD,E007450,TPC50D30; tolerance: N/A
U1 = ADMAX3265X: Tolerance: N/A; User Part Number: UPN; alternate symbols: (QFP144-4); part number: ADMAX3265X_SM-MAX32650GCE+,E058988,QFP144-4; tolerance: N/A
U2 = AD74413: User Part Number: UPN; Tolerance: N/A; alternate symbols: (QFN64_9X9_PAD7_6X7_6); part number: AD74413_SM-AD74413RBCPZ,E030780,QFN64_9X9_PAD7_6X7_6; tolerance: N/A
U3 = ADMAX14906: User Part Number: UPN; Tolerance: N/A; alternate symbols: (QFN48_7X7_PAD5_5X5_5); part number: ADMAX14906_SM-MAX14906ATM+,E058256,QFN48_7X7_PAD5_5X5_5; tolerance: N/A
U4 = ADT75: Tolerance: N/A; User Part Number: UPN; alternate symbols: (MSOP8); part number: ADT75_SM-ADT75BRMZ,E029518,MSOP8; tolerance: N/A
U5 = ADMAXQ1065: User Part Number: UPN; Tolerance: N/A; alternate symbols: (DFN12_3X3_PAD2_5X1_7); part number: ADMAXQ1065_SM-MAXQ1065GTC+,E059230,DFN12_3X3_PAD2_5X1_7; tolerance: N/A
U6 U7 U14 = ADMAX14483: Tolerance: N/A; User Part Number: UPN; alternate symbols: (SSOP20-6); part number: ADMAX14483_SM-MAX14483AAP+,E058258,SSOP20-6; tolerance: N/A
U8 = ADIN1110_V2: User Part Number: UPN; Tolerance: N/A; alternate symbols: (QFN40_6X6_PAD3_5X3_5); part number: ADIN1110_V2_SM-ADIN1110CCPZ,E049968,QFN40_6X6_PAD3_5X3_5; tolerance: N/A
U9 U10 = ICS80KS5122: Tolerance: N/A; User Part Number: UPN; alternate symbols: (BGA24_8X6_PB); part number: ICS80KS5122_SM-S80KS5122GABHM020,E060311,BGA24_8X6; tolerance: N/A
U11 = ICMX25U6432F_V2: User Part Number: UPN; Tolerance: N/A; alternate symbols: (SOP8_A); part number: ICMX25U6432F_V2_SM-MX25U6432FM2I02,E060310,SOP8_A; tolerance: N/A
U12 U13 = ADMAX14933: Tolerance: N/A; User Part Number: UPN; alternate symbols: (SO16NB-2); part number: ADMAX14933_SM-MAX14933ASE+,E060481,SO16NB-2; tolerance: N/A
U15 = ADLT8304: Tolerance: N/A; User Part Number: UPN; alternate symbols: (SO8NB_PAD3_27X2_28-05-08-1857); part number: ADLT8304_SM-LT8304IS8E#PBF,E061426,SO8NB_PAD3_27X2_28-05-08-1857; tolerance: N/A
U16 = ADMAX17761: User Part Number: UPN; Tolerance: N/A; alternate symbols: (DFN12_3X3_PAD2_5X1_7); part number: ADMAX17761_SM-MAX17761ATC+,E061359,DFN12_3X3_PAD2_5X1_7; tolerance: N/A
U17 = ADP22X: User Part Number: UPN; Tolerance: N/A; alternate symbols: (QFN8_2X2_PAD1_6X1); part number: ADP22X_SM-ADP225ACPZ,E016555,QFN8_2X2_PAD1_6X1; tolerance: N/A
U18 = ADMAX12930: Tolerance: N/A; User Part Number: UPN; alternate symbols: (SO8NB-5); part number: ADMAX12930_SM-MAX12930EASA+,E062639,SO8NB-5; tolerance: N/A
U19 = ADLTC9111_V2: User Part Number: UPN; Tolerance: N/A; alternate symbols: (DFN12_4X3_PAD3_3X1_7-05-08-1695); part number: ADLTC9111_V2_SM-LTC9111RDE#PBF,E060683,DFN12_4X3_PAD3_3X1_7-05-08-1695; tolerance: N/A
U25 = ADP1032: Tolerance: N/A; User Part Number: UPN; alternate symbols: (QFN41_7X9_3PAD); part number: ADP1032_SM-ADP1032ACPZ-5,E035169,QFN41_7X9_3PAD; tolerance: N/A
Y1 = XTAL4PIN_V3: Tolerance: 10PPM; User Part Number: UPN; alternate symbols: (YSML79W63H20); part number: XTAL4PIN_V3_SM-25MEGHZ,E051324,YSML79W63H20; tolerance: 10PPM

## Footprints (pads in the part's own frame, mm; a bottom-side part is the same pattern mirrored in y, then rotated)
BGA24_8X6
  round 0.305 smd: A2(-2,-1) A3(-2,0) A4(-2,1) A5(-2,2) B1(-1,-2) B2(-1,-1) B3(-1,0) B4(-1,1) B5(-1,2) C1(0,-2) C2(0,-1) C3(0,0) C4(0,1) C5(0,2) D1(1,-2) D2(1,-1) D3(1,0) D4(1,1) D5(1,2) E1(2,-2) E2(2,-1) E3(2,0) E4(2,1) E5(2,2)
C0402
  rect 0.483x0.559 smd: 1(-0.45,0) 2(0.45,0)
C0402H22
  rect 0.483x0.559 smd: 1(-0.45,0) 2(0.45,0)
C0603
  rect 0.762x0.889 smd: 1(-0.7,0) 2(0.7,0)
C0603#2
  rect 0.94x0.991 smd: 1(-0.8,0) 2(0.8,0)
C0805
  rect 1.016x1.372 smd: 1(-0.803,0) 2(0.803,0)
C0805H55
  rect 1.143x1.448 smd: 1(-0.9,0) 2(0.9,0)
C0805H60
  rect 1.295x1.6 smd: 1(-0.953,0) 2(0.953,0)
C1206
  rect 0.94x1.702 smd: 1(-1.4,0) 2(1.4,0)
C1206H71
  rect 0.94x1.702 smd: 1(-1.4,0) 2(1.4,0)
C1210-2
  rect 1.575x2.692 smd: 1(-1.397,0) 2(1.397,0)
C1210H67
  rect 1.194x2.692 smd: 1(-1.448,0) 2(1.448,0)
C1210H87
  rect 1.092x2.21 smd: 1(-1.646,0) 2(1.646,0)
C1812H71
  rect 1.397x3.505 smd: 1(-2.05,0) 2(2.05,0)
CNCUITBP02R2-381-03
  rect 1.905x1.905 hole 1.397: 1(0,0)
  round 1.905 hole 1.397: 2(3.81,0) 3(7.62,0)
CNCUITBP02R2-381-08
  rect 1.905x1.905 hole 1.397: 1(0,0)
  round 1.905 hole 1.397: 2(3.81,0) 3(7.62,0) 4(11.43,0) 5(15.24,0) 6(19.05,0) 7(22.86,0) 8(26.67,0)
CNCUITBP04R2-500-02
  rect 2.159x2.159 hole 1.651: 1(0,0)
  round 2.159 hole 1.651: 2(5,0)
CNHDR2X5H245
  rect 0.737x2.794 smd: 1(-2.54,-2.032) 2(-2.54,2.032) 3(-1.27,-2.032) 4(-1.27,2.032) 5(0,-2.032) 6(0,2.032) 7(1.27,-2.032) 8(1.27,2.032) 9(2.54,-2.032) 10(2.54,2.032)
CNRCPT2X6H335LD35
  rect 1.651x1.651 hole 1.143: 1(0,0)
  round 1.651 hole 1.143: 2(0,-2.54) 3(2.54,0) 4(2.54,-2.54) 5(5.08,0) 6(5.08,-2.54) 7(7.62,0) 8(7.62,-2.54) 9(10.16,0) 10(10.16,-2.54) 11(12.7,0) 12(12.7,-2.54)
CPLSMSQ260H240_A
  rect 3.15x1.6 smd: N(2.9,0) P(-2.9,0)
CPLSMSQ327H276
  rect 3.454x1.956 smd: N(3.35,0) P(-3.35,0)
D2038
  rect 1.6x5.588 smd: 1(-3.3,0) 2(3.3,0) 3(0,0)
DFN12_3X3_PAD2_5X1_7
  oval 0.279x0.737 smd: 1(-1.25,-1.43) 2(-0.75,-1.43) 3(-0.25,-1.43) 4(0.25,-1.43) 5(0.75,-1.43) 6(1.25,-1.43) 7(1.25,1.43) 8(0.75,1.43) 9(0.25,1.43) 10(-0.25,1.43) 11(-0.75,1.43) 12(-1.25,1.43)
  rect 2.489x1.702 smd: PAD(0,0)
DFN12_4X3_PAD3_3X1_7-05-08-1695
  oval 0.254x0.737 smd: 1(-1.25,-1.46) 2(-0.75,-1.46) 3(-0.25,-1.46) 4(0.25,-1.46) 5(0.75,-1.46) 6(1.25,-1.46) 7(1.25,1.46) 8(0.75,1.46) 9(0.25,1.46) 10(-0.25,1.46) 11(-0.75,1.46) 12(-1.25,1.46)
  rect 3.302x1.702 smd: 13(0,0)
DO214AA-5
  rect 2.489x2.21 smd: 1(-2.35,0) 2(2.35,0)
DO214AB_A
  rect 2.388x3.277 smd: 1(-3.289,0) 2(3.289,0)
JPRSLD03
  rect 0.61x1.524 smd: 1(-0.838,0) 2(0,0) 3(0.838,0)
L0402-3
  rect 0.457x0.508 smd: 1(-0.479,0) 2(0.479,0)
LED0402_A
  rect 0.711x0.508 smd: A(0.555,0) C(-0.555,0)
LED0402H24
  rect 0.711x0.508 smd: A(0.555,0) C(-0.555,0)
LSML208W216H201
  rect 1.168x4.699 smd: 1(-1.651,0) 2(1.651,0)
LSML236W362H209
  rect 1.194x2.007 smd: 1(-1.27,-3.747) 2(1.27,-3.747) 3(1.27,3.747) 4(-1.27,3.747)
LSMSQ118H47
  rect 0.991x3.2 smd: 1(-0.995,0) 2(0.995,0)
LSMSQ406H197
  rect 2.388x1.245 smd: 1(-3.899,1.029) 2(-3.899,-1.029) 3(3.899,-1.029) 4(3.899,1.029)
MSOP8
  rect 0.305x1.321 smd: 1(-0.975,-2.3) 2(-0.325,-2.3) 3(0.325,-2.3) 4(0.975,-2.3) 5(0.975,2.3) 6(0.325,2.3) 7(-0.325,2.3) 8(-0.975,2.3)
POWERDI123
  rect 0.889x1.397 smd: A(1.606,0)
  rect 2.21x1.397 smd: C(-0.945,0)
POWERPAK1212-8_SP
  rect 0.406x0.991 smd: 1(-0.991,-1.435) 2(-0.33,-1.435) 3(0.33,-1.435) 4(0.991,-1.435)
  round 0.127 smd: 5(0.991,1.676) 6(0.33,1.676) 7(-0.33,1.676)
  custom 0.559x0.559 smd: 8(-0.991,1.676)
QFN8_2X2_PAD1_6X1
  oval 0.305x0.864 smd: 1(-0.75,-1.13) 2(-0.25,-1.13) 3(0.25,-1.13) 4(0.75,-1.13) 5(0.75,1.13) 6(0.25,1.13) 7(-0.25,1.13) 8(-0.75,1.13)
  rect 1.6x0.991 smd: PAD(0,0)
QFN40_6X6_PAD3_5X3_5
  oval 0.279x0.737 smd: 1(-2.25,-2.893) 2(-1.75,-2.893) 3(-1.25,-2.893) 4(-0.75,-2.893) 5(-0.25,-2.893) 6(0.25,-2.893) 7(0.75,-2.893) 8(1.25,-2.893) 9(1.75,-2.893) 10(2.25,-2.893) 21(2.25,2.893) 22(1.75,2.893) 23(1.25,2.893) 24(0.75,2.893) 25(0.25,2.893) 26(-0.25,2.893) 27(-0.75,2.893) 28(-1.25,2.893) 29(-1.75,2.893) 30(-2.25,2.893)
  oval 0.737x0.279 smd: 11(2.893,-2.25) 12(2.893,-1.75) 13(2.893,-1.25) 14(2.893,-0.75) 15(2.893,-0.25) 16(2.893,0.25) 17(2.893,0.75) 18(2.893,1.25) 19(2.893,1.75) 20(2.893,2.25) 31(-2.893,2.25) 32(-2.893,1.75) 33(-2.893,1.25) 34(-2.893,0.75) 35(-2.893,0.25) 36(-2.893,-0.25) 37(-2.893,-0.75) 38(-2.893,-1.25) 39(-2.893,-1.75) 40(-2.893,-2.25)
  rect 3.505x3.505 smd: PAD(0,0)
QFN41_7X9_3PAD
  oval 0.305x0.787 smd: 1(-2.75,-4.5) 2(-2.25,-4.5) 3(-1.75,-4.5) 4(1.25,-4.5) 5(1.75,-4.5) 6(2.25,-4.5) 7(2.75,-4.5) 24(2.75,4.5) 25(2.25,4.5) 26(1.75,4.5) 27(1.25,4.5) 28(-1.75,4.5) 29(-2.25,4.5) 30(-2.75,4.5)
  oval 0.787x0.305 smd: 8(3.5,-3.75) 9(3.5,-3.25) 10(3.5,-2.75) 11(3.5,-2.25) 12(3.5,-1.75) 13(3.5,-1.25) 14(3.5,-0.75) 15(3.5,-0.25) 16(3.5,0.25) 17(3.5,0.75) 18(3.5,1.25) 19(3.5,1.75) 20(3.5,2.25) 21(3.5,2.75) 22(3.5,3.25) 23(3.5,3.75) 31(-3.5,3.75) 32(-3.5,3.25) 33(-3.5,2.75) 34(-3.5,-0.25) 35(-3.5,-0.75) 36(-3.5,-1.25) 37(-3.5,-1.75) 38(-3.5,-2.25) 39(-3.5,-2.75) 40(-3.5,-3.25) 41(-3.5,-3.75)
  rect 2.083x7.696 smd: PAD1(1.808,0)
  rect 1.397x1.626 smd: PAD2(-2.139,2.989)
  rect 1.397x3.785 smd: PAD3(-2.139,-1.914)
QFN48_7X7_PAD5_5X5_5
  oval 0.305x0.94 smd: 1(-2.75,-3.5) 2(-2.25,-3.5) 3(-1.75,-3.5) 4(-1.25,-3.5) 5(-0.75,-3.5) 6(-0.25,-3.5) 7(0.25,-3.5) 8(0.75,-3.5) 9(1.25,-3.5) 10(1.75,-3.5) 11(2.25,-3.5) 12(2.75,-3.5) 25(2.75,3.5) 26(2.25,3.5) 27(1.75,3.5) 28(1.25,3.5) 29(0.75,3.5) 30(0.25,3.5) 31(-0.25,3.5) 32(-0.75,3.5) 33(-1.25,3.5) 34(-1.75,3.5) 35(-2.25,3.5) 36(-2.75,3.5)
  oval 0.94x0.305 smd: 13(3.5,-2.75) 14(3.5,-2.25) 15(3.5,-1.75) 16(3.5,-1.25) 17(3.5,-0.75) 18(3.5,-0.25) 19(3.5,0.25) 20(3.5,0.75) 21(3.5,1.25) 22(3.5,1.75) 23(3.5,2.25) 24(3.5,2.75) 37(-3.5,2.75) 38(-3.5,2.25) 39(-3.5,1.75) 40(-3.5,1.25) 41(-3.5,0.75) 42(-3.5,0.25) 43(-3.5,-0.25) 44(-3.5,-0.75) 45(-3.5,-1.25) 46(-3.5,-1.75) 47(-3.5,-2.25) 48(-3.5,-2.75)
  rect 5.512x5.512 smd: PAD(0,0)
QFN64_9X9_PAD7_6X7_6
  oval 0.305x0.838 smd: 1(-3.75,-4.519) 2(-3.25,-4.519) 3(-2.75,-4.519) 4(-2.25,-4.519) 5(-1.75,-4.519) 6(-1.25,-4.519) 7(-0.75,-4.519) 8(-0.25,-4.519) 9(0.25,-4.519) 10(0.75,-4.519) 11(1.25,-4.519) 12(1.75,-4.519) 13(2.25,-4.519) 14(2.75,-4.519) 15(3.25,-4.519) 16(3.75,-4.519) 33(3.75,4.519) 34(3.25,4.519) 35(2.75,4.519) 36(2.25,4.519) 37(1.75,4.519) 38(1.25,4.519) 39(0.75,4.519) 40(0.25,4.519) 41(-0.25,4.519) 42(-0.75,4.519) 43(-1.25,4.519) 44(-1.75,4.519) 45(-2.25,4.519) 46(-2.75,4.519) 47(-3.25,4.519) 48(-3.75,4.519)
  oval 0.838x0.305 smd: 17(4.519,-3.75) 18(4.519,-3.25) 19(4.519,-2.75) 20(4.519,-2.25) 21(4.519,-1.75) 22(4.519,-1.25) 23(4.519,-0.75) 24(4.519,-0.25) 25(4.519,0.25) 26(4.519,0.75) 27(4.519,1.25) 28(4.519,1.75) 29(4.519,2.25) 30(4.519,2.75) 31(4.519,3.25) 32(4.519,3.75) 49(-4.519,3.75) 50(-4.519,3.25) 51(-4.519,2.75) 52(-4.519,2.25) 53(-4.519,1.75) 54(-4.519,1.25) 55(-4.519,0.75) 56(-4.519,0.25) 57(-4.519,-0.25) 58(-4.519,-0.75) 59(-4.519,-1.25) 60(-4.519,-1.75) 61(-4.519,-2.25) 62(-4.519,-2.75) 63(-4.519,-3.25) 64(-4.519,-3.75)
  rect 7.595x7.595 smd: PAD(0,0)
QFP144-4
  rect 0.254x1.524 smd: 1(-8.75,-10.74) 2(-8.25,-10.74) 3(-7.75,-10.74) 4(-7.25,-10.74) 5(-6.75,-10.74) 6(-6.25,-10.74) 7(-5.75,-10.74) 8(-5.25,-10.74) 9(-4.75,-10.74) 10(-4.25,-10.74) 11(-3.75,-10.74) 12(-3.25,-10.74) 13(-2.75,-10.74) 14(-2.25,-10.74) 15(-1.75,-10.74) 16(-1.25,-10.74) 17(-0.75,-10.74) 18(-0.25,-10.74) 19(0.25,-10.74) 20(0.75,-10.74) 21(1.25,-10.74) 22(1.75,-10.74) 23(2.25,-10.74) 24(2.75,-10.74) 25(3.25,-10.74) 26(3.75,-10.74) 27(4.25,-10.74) 28(4.75,-10.74) 29(5.25,-10.74) 30(5.75,-10.74) 31(6.25,-10.74) 32(6.75,-10.74) 33(7.25,-10.74) 34(7.75,-10.74) 35(8.25,-10.74) 36(8.75,-10.74) 73(8.75,10.74) 74(8.25,10.74) 75(7.75,10.74) 76(7.25,10.74) 77(6.75,10.74) 78(6.25,10.74) 79(5.75,10.74) 80(5.25,10.74) 81(4.75,10.74) 82(4.25,10.74) 83(3.75,10.74) 84(3.25,10.74) 85(2.75,10.74) 86(2.25,10.74) 87(1.75,10.74) 88(1.25,10.74) 89(0.75,10.74) 90(0.25,10.74) 91(-0.25,10.74) 92(-0.75,10.74) 93(-1.25,10.74) 94(-1.75,10.74) 95(-2.25,10.74) 96(-2.75,10.74) 97(-3.25,10.74) 98(-3.75,10.74) 99(-4.25,10.74) 100(-4.75,10.74) 101(-5.25,10.74) 102(-5.75,10.74) 103(-6.25,10.74) 104(-6.75,10.74) 105(-7.25,10.74) 106(-7.75,10.74) 107(-8.25,10.74) 108(-8.75,10.74)
  rect 1.524x0.254 smd: 37(10.74,-8.75) 38(10.74,-8.25) 39(10.74,-7.75) 40(10.74,-7.25) 41(10.74,-6.75) 42(10.74,-6.25) 43(10.74,-5.75) 44(10.74,-5.25) 45(10.74,-4.75) 46(10.74,-4.25) 47(10.74,-3.75) 48(10.74,-3.25) 49(10.74,-2.75) 50(10.74,-2.25) 51(10.74,-1.75) 52(10.74,-1.25) 53(10.74,-0.75) 54(10.74,-0.25) 55(10.74,0.25) 56(10.74,0.75) 57(10.74,1.25) 58(10.74,1.75) 59(10.74,2.25) 60(10.74,2.75) 61(10.74,3.25) 62(10.74,3.75) 63(10.74,4.25) 64(10.74,4.75) 65(10.74,5.25) 66(10.74,5.75) 67(10.74,6.25) 68(10.74,6.75) 69(10.74,7.25) 70(10.74,7.75) 71(10.74,8.25) 72(10.74,8.75) 109(-10.74,8.75) 110(-10.74,8.25) 111(-10.74,7.75) 112(-10.74,7.25) 113(-10.74,6.75) 114(-10.74,6.25) 115(-10.74,5.75) 116(-10.74,5.25) 117(-10.74,4.75) 118(-10.74,4.25) 119(-10.74,3.75) 120(-10.74,3.25) 121(-10.74,2.75) 122(-10.74,2.25) 123(-10.74,1.75) 124(-10.74,1.25) 125(-10.74,0.75) 126(-10.74,0.25) 127(-10.74,-0.25) 128(-10.74,-0.75) 129(-10.74,-1.25) 130(-10.74,-1.75) 131(-10.74,-2.25) 132(-10.74,-2.75) 133(-10.74,-3.25) 134(-10.74,-3.75) 135(-10.74,-4.25) 136(-10.74,-4.75) 137(-10.74,-5.25) 138(-10.74,-5.75) 139(-10.74,-6.25) 140(-10.74,-6.75) 141(-10.74,-7.25) 142(-10.74,-7.75) 143(-10.74,-8.25) 144(-10.74,-8.75)
R0402
  rect 0.483x0.559 smd: 1(-0.45,0) 2(0.45,0)
R0603
  rect 0.787x0.991 smd: 1(-0.85,0) 2(0.85,0)
R0805
  rect 0.838x1.295 smd: 1(-0.85,0) 2(0.85,0)
R2010
  rect 1.905x2.794 smd: 1(-2.286,0) 2(2.286,0)
SO8NB-5
  rect 0.635x1.829 smd: 1(-1.905,-2.591) 2(-0.635,-2.591) 3(0.635,-2.591) 4(1.905,-2.591) 5(1.905,2.591) 6(0.635,2.591) 7(-0.635,2.591) 8(-1.905,2.591)
SO8NB_PAD3_27X2_28-05-08-1857
  rect 0.635x1.905 smd: 1(-1.905,-2.49) 2(-0.635,-2.49) 3(0.635,-2.49) 4(1.905,-2.49) 5(1.905,2.49) 6(0.635,2.49) 7(-0.635,2.49) 8(-1.905,2.49)
  rect 3.277x2.286 smd: 9(0,0)
SO16NB-2
  rect 0.635x1.829 smd: 1(-4.445,-2.591) 2(-3.175,-2.591) 3(-1.905,-2.591) 4(-0.635,-2.591) 5(0.635,-2.591) 6(1.905,-2.591) 7(3.175,-2.591) 8(4.445,-2.591) 9(4.445,2.591) 10(3.175,2.591) 11(1.905,2.591) 12(0.635,2.591) 13(-0.635,2.591) 14(-1.905,2.591) 15(-3.175,2.591) 16(-4.445,2.591)
SOD123-2
  rect 0.914x1.219 smd: A(1.638,0) C(-1.638,0)
SOD123F
  rect 1.194x1.194 smd: A(1.403,0) C(-1.403,0)
SOD128
  rect 0.991x1.93 smd: A(2.21,0) C(-2.21,0)
SOD323-2
  rect 0.94x0.813 smd: A(1.28,0) C(-1.28,0)
SOD323_B
  rect 0.889x0.508 smd: 1(-1.3,0) 2(1.3,0)
SOP8_A
  rect 0.61x1.6 smd: 1(-1.905,-3.594) 2(-0.635,-3.594) 3(0.635,-3.594) 4(1.905,-3.594) 5(1.905,3.594) 6(0.635,3.594) 7(-0.635,3.594) 8(-1.905,3.594)
SOT23
  rect 1.016x1.397 smd: 1(-0.94,-1.118) 2(0.94,-1.118) 3(0,1.118)
SOT26-2
  rect 0.559x1.092 smd: 1(-0.95,-1.2) 2(0,-1.2) 3(0.95,-1.2) 4(0.95,1.2) 5(0,1.2) 6(-0.95,1.2)
SOT323
  rect 0.711x0.889 smd: 1(-0.635,-0.953) 2(0.635,-0.953) 3(0,0.953)
SOT1205
  rect 0.711x1.143 smd: 1(-1.905,-3.278) 2(-0.635,-3.278) 3(0.635,-3.278) 4(1.905,-3.278)
  custom 0.495x0.495 smd: 5(1.905,2.26) 7(-0.635,2.26)
  round 0.127 smd: 6(0.635,2.54) 8(-1.905,2.54)
SOT1210
  rect 0.457x1.041 smd: 1(-0.975,-1.65) 2(-0.325,-1.65) 3(0.325,-1.65) 4(0.975,-1.65)
  round 0.127 smd: 5(0.975,1.65) 6(0.325,1.65) 7(-0.325,1.65) 8(-0.975,1.65)
SSOP20-6
  rect 0.33x1.778 smd: 1(-2.925,-3.5) 2(-2.275,-3.5) 3(-1.625,-3.5) 4(-0.975,-3.5) 5(-0.325,-3.5) 6(0.325,-3.5) 7(0.975,-3.5) 8(1.625,-3.5) 9(2.275,-3.5) 10(2.925,-3.5) 11(2.925,3.5) 12(2.275,3.5) 13(1.625,3.5) 14(0.975,3.5) 15(0.325,3.5) 16(-0.325,3.5) 17(-0.975,3.5) 18(-1.625,3.5) 19(-2.275,3.5) 20(-2.925,3.5)
SWSML118W98H69
  rect 0.787x1.702 smd: 1(-1.694,0) 2(1.694,0)
SWTHL449W500H561
  rect 2.286x2.286 hole 1.778: 1(0,0)
  round 2.286 hole 1.778: 2(0,4.699) 3(0,9.398) 4(4.801,0) 5(4.801,4.699) 6(4.801,9.398)
TPC50D30
  round 1.27 hole 0.762: 1(0,0)
TSML430W364H394
  rect 1.6x2.438 smd: 1(-3.75,-3.669) 2(-1.25,-3.669) 3(1.25,-3.669) 4(3.75,-3.669) 5(3.75,3.669) 6(1.25,3.669) 7(-1.25,3.669) 8(-3.75,3.669)
TSMSQ530H505
  rect 1.168x1.88 smd: 1(-4.978,8.179) 2(-2.489,8.179) 3(0,8.179) 4(2.489,8.179) 5(4.978,8.179) 6(4.978,-8.179) 7(2.489,-8.179) 8(0,-8.179) 9(-2.489,-8.179) 10(-4.978,-8.179)
unnamed#2
  round 1.016 smd: (0,0)
YSML79W63H20
  rect 0.94x0.838 smd: 1(-0.725,-0.575) 2(0.725,-0.575) 3(0.725,0.575) 4(-0.725,0.575)

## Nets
1V1: C78.1 C79.1 C80.1 C125.1 R43.1 TP15.1(N1) U1.5 U1.14 U1.88 U17.7
1V8: C62.2(N2) C63.2(N2) C64.2(N2) C65.2(N2) C66.2(N2) C67.2(N2) C68.2(N2) C69.2(N2) C82.1 C83.1 C84.2(N2) C85.1 C86.1 C87.1 C88.2(N2) C89.2(N2) C90.2(N2) C91.1 C92.1 C93.1 C94.2(N2) C95.2(N2) C96.1 C101.1 C124.1 C142.1 P1.1 R45.1 R82.1 TP13.1(N1) U1.21 U1.33 U1.55 U1.99 U1.111 U1.126 U9.B4 U9.D1 U9.E4 U10.B4 U10.D1 U10.E4 U11.8 U17.5(VOUT2)
3V3: C59.1 C61.2(N2) C70.1 C71.1 C72.1 C73.1 C74.1 C75.1 C76.1 C77.1 C81.1 C97.1 C98.2(N2) C99.1 C102.1 C103.1 C107.1 C108.2(N2) C109.2(N2) C121.2(N2) C123.1 C146.1 DS10.A(P) DS11.A(P) E1.1 E2.1 R35.2(N2) R57.1 R65.2(N2) R81.1 R94.1 R95.1 R96.1 R104.1 R116.1 R117.1 R125.1 R127.1 R128.1 R129.1 R130.1 U1.9 U1.18 U1.54 U1.76 U1.128 U4.8(VDD) U5.12 U6.20(VDDB) U7.20(VDDB) U8.35 U12.3 U13.3 U14.1 U17.1 U17.2 U17.6 U18.8(VDDB) U25.39
3V3_ISO: C28.2(N2) C29.2(N2) C30.2(N2) C31.2(N2) C44.2(N2) C104.2(N2) C105.2(N2) C110.2(N2) C111.2(N2) C112.2(N2) C128.2(N2) C129.2(N2) C147.2(N2) P2.11 P2.12 R48.1 R58.2(N2) R69.1 R75.1 R77.1 R79.1 R84.1 R132.1 R133.1 R134.1 R135.1 U2.23 U2.55 U2.56 U3.12 U3.25 U6.1 U7.1 U12.14(VDDB) U13.14(VDDB) U14.20(VDDB) U18.1 U25.10 U25.20
3V3_O: C132.1 L4.2(N2) R60.1 R65.1 TP11.1(N1)
24V_EXT: C116.1 C141.1 C144.P D13.A(P) D17.2(N2) P4.2(N2) R29.2(N2) S2.4 T2.5 U15.3(VIN)
36V: C134.P C140.P C145.2(N2) D16.C D18.A(P) TP5.1(N1)
